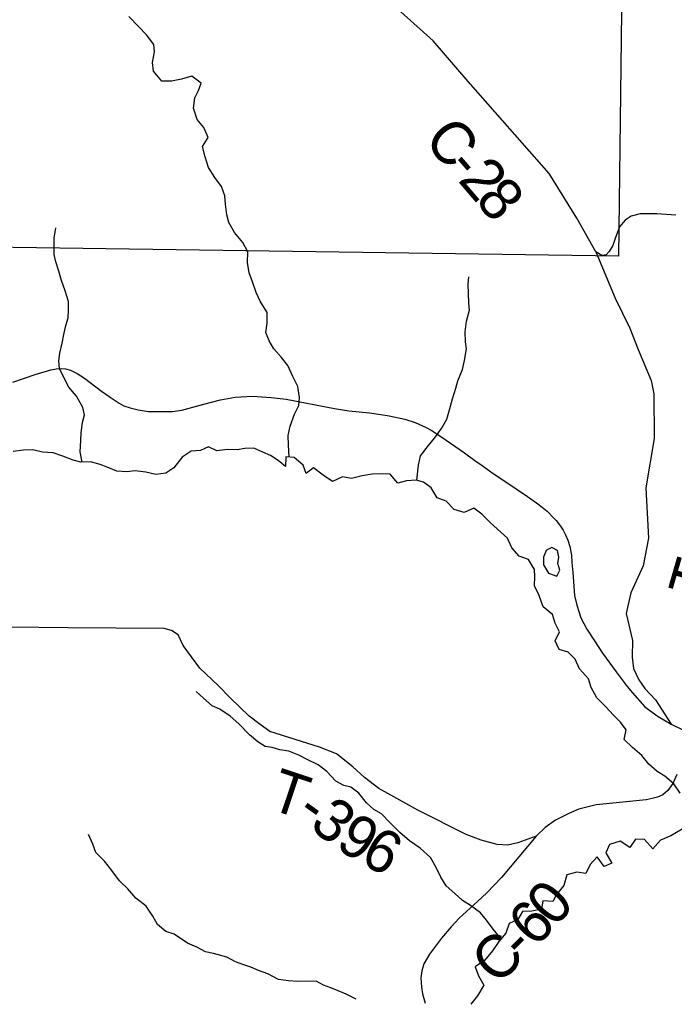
# Model space of a CAD drawing. Extents: x -20.5 to 34, y -66 to 23.9.
# Drawn here: x 7.132 to 8.003, y 16.344 to 17.643 of the extents above; entities that cross this region are included whole.
import ezdxf

# ---------------------------------------------------------------- set-up
doc = ezdxf.new("R2010")
doc.units = 0
for name, color, linetype in [('GM_X_County_Text', 7, 'Continuous'), ('GM_X_Minor_Lake', 7, 'Continuous'), ('GM_X_Minor_River', 7, 'Continuous'), ('GM_X_Minor_River_Text', 7, 'Continuous'), ('GM_X_Section_Text', 7, 'Continuous'), ('GM_X_State_Route', 7, 'Continuous'), ('GM_X_Township_Road', 7, 'Continuous'), ('GM_X_Township_Road_Text', 7, 'Continuous')]:
    doc.layers.add(name, color=color, linetype=linetype)

msp = doc.modelspace()

# ---------------------------------------------------------------- linework, layer by layer
at = {"layer": 'GM_X_County_Text'}
for points in [[(7.8986, 17.3346), (7.924, 17.2728), (7.9438, 17.2332), (7.9545, 17.2047), (7.9719, 17.1637), (7.9754, 17.1456), (7.9761, 17.0866), (7.9647, 17.0209), (7.9685, 16.9541), (7.9614, 16.9171), (7.9451, 16.8813), (7.9422, 16.87), (7.9386, 16.8541), (7.947, 16.8183), (7.9466, 16.7959), (7.9483, 16.7807), (7.9555, 16.7657), (7.9637, 16.7545), (7.9778, 16.7393), (7.9984, 16.7071)], [(7.8192, 16.5583), (7.7947, 16.5495), (7.7812, 16.5464), (7.7672, 16.5472), (7.7458, 16.5528), (7.726, 16.5606), (7.6616, 16.5929), (7.6098, 16.6215), (7.591, 16.6362), (7.5753, 16.6501), (7.5535, 16.6677), (7.531, 16.6763), (7.465, 16.6974), (7.4522, 16.7067), (7.4378, 16.7175), (7.4129, 16.7415), (7.3962, 16.7582), (7.3721, 16.7815), (7.3497, 16.8115), (7.3432, 16.8256), (7.3342, 16.8316), (7.3246, 16.834), (7.1972, 16.835), (7.119, 16.8357)]]:
    msp.add_lwpolyline(points, dxfattribs=at)
at = {"layer": 'GM_X_Minor_Lake'}
msp.add_lwpolyline([(7.9409, 18.3387), (7.9284, 17.3287), (7.0924, 17.3404), (6.9259, 17.3432), (6.9356, 18.3607)], close=True, dxfattribs=at)
at = {"layer": 'GM_X_Minor_River'}
for points in [[(7.8355, 16.9394), (7.8322, 16.9377), (7.8289, 16.9289), (7.8287, 16.9187), (7.8354, 16.9074), (7.8467, 16.9034)], [(7.8467, 16.9034), (7.8507, 16.9114), (7.848, 16.9205), (7.8493, 16.9289), (7.8473, 16.9376), (7.8401, 16.9416), (7.8355, 16.9394)]]:
    msp.add_lwpolyline(points, dxfattribs=at)
at = {"layer": 'GM_X_Minor_River_Text'}
for points in [[(7.4906, 17.0619), (7.4899, 17.0775), (7.4893, 17.0904), (7.4922, 17.103), (7.498, 17.1186), (7.5035, 17.1301), (7.5044, 17.1411), (7.5023, 17.1555), (7.4957, 17.169), (7.489, 17.1833), (7.4805, 17.1942), (7.4702, 17.2054), (7.4643, 17.216), (7.4596, 17.2273), (7.4617, 17.2398), (7.4615, 17.2539), (7.4522, 17.2689), (7.4467, 17.2806), (7.4419, 17.2946), (7.4376, 17.3066), (7.4355, 17.3203), (7.436, 17.3343), (7.429, 17.3467), (7.4182, 17.3602), (7.4105, 17.3734), (7.408, 17.3836), (7.4063, 17.3976), (7.4054, 17.4086), (7.4007, 17.421), (7.3918, 17.433), (7.3836, 17.4466), (7.3793, 17.4605), (7.3756, 17.4741), (7.383, 17.4864), (7.3775, 17.4996), (7.3683, 17.5104), (7.3635, 17.5252), (7.3652, 17.5388), (7.3703, 17.5488), (7.374, 17.5583), (7.3613, 17.5676), (7.3478, 17.5636), (7.3342, 17.5611), (7.3217, 17.5609), (7.3105, 17.5744), (7.3092, 17.5858), (7.3117, 17.6002), (7.3108, 17.6097), (7.3011, 17.6225), (7.2903, 17.6337), (7.2776, 17.6471)], [(7.2156, 17.0548), (7.213, 17.0688), (7.2139, 17.084), (7.2142, 17.0939), (7.2162, 17.1075), (7.2187, 17.1178), (7.2167, 17.1277), (7.2081, 17.1427), (7.1977, 17.1547), (7.1911, 17.1675), (7.1856, 17.1795), (7.1847, 17.1898), (7.1861, 17.2), (7.1889, 17.213), (7.1914, 17.2248), (7.1938, 17.2366), (7.1971, 17.2469), (7.1973, 17.2567), (7.1975, 17.2685), (7.1931, 17.2825), (7.188, 17.2964), (7.1844, 17.3089), (7.1805, 17.321), (7.1784, 17.3308), (7.1783, 17.341), (7.1785, 17.3524), (7.1805, 17.3661)], [(7.6604, 17.0309), (7.6625, 17.0509), (7.6653, 17.0635), (7.6761, 17.0773), (7.6839, 17.0869), (7.6935, 17.0999), (7.7005, 17.1122), (7.7041, 17.1244), (7.7077, 17.1392), (7.7124, 17.1533), (7.7149, 17.1632), (7.7211, 17.1781), (7.7239, 17.1899), (7.7263, 17.2055), (7.7254, 17.215), (7.7248, 17.2282), (7.7265, 17.2423), (7.7305, 17.2568), (7.7296, 17.2666), (7.729, 17.2787), (7.7288, 17.2913), (7.7294, 17.3011)], [(8.0107, 16.6152), (8.0022, 16.6276), (7.99, 16.6377), (7.98, 16.644), (7.9689, 16.6537), (7.9597, 16.6653), (7.9474, 16.6761), (7.9362, 16.6866), (7.9387, 16.6995), (7.9314, 16.7097), (7.9218, 16.719), (7.9118, 16.7302), (7.8998, 16.7418), (7.8924, 16.7557), (7.8889, 16.7671), (7.8766, 16.7805), (7.8711, 16.7934), (7.8615, 16.8027), (7.8497, 16.8063), (7.8446, 16.8176), (7.8501, 16.8295), (7.8442, 16.8411), (7.8407, 16.8525), (7.8284, 16.8629), (7.8229, 16.878), (7.817, 16.8908), (7.8172, 16.903), (7.817, 16.9125), (7.8089, 16.9256), (7.7967, 16.93), (7.7867, 16.9412), (7.7808, 16.954), (7.7678, 16.966), (7.7574, 16.9753), (7.7471, 16.9861), (7.7363, 16.994), (7.7236, 16.9881), (7.7103, 16.992), (7.6995, 17.0033), (7.6877, 17.0076), (7.6796, 17.0208), (7.6692, 17.0286), (7.6597, 17.0311), (7.6469, 17.0302), (7.6352, 17.027), (7.6252, 17.039), (7.6153, 17.0396), (7.6013, 17.039), (7.5877, 17.0369), (7.5738, 17.0332), (7.5617, 17.0357), (7.5485, 17.0295), (7.5359, 17.0376), (7.5233, 17.0473), (7.5135, 17.0399), (7.5096, 17.0509), (7.4973, 17.0613), (7.4863, 17.0623), (7.4858, 17.0494), (7.4762, 17.0572), (7.4659, 17.0639), (7.4556, 17.0683), (7.4438, 17.0734), (7.4317, 17.0732), (7.4215, 17.0712), (7.409, 17.0717), (7.3946, 17.07), (7.3836, 17.0752), (7.3731, 17.0705), (7.3606, 17.0695), (7.3486, 17.0617), (7.3375, 17.0475), (7.327, 17.0405), (7.3134, 17.0388), (7.3001, 17.0417), (7.2861, 17.0433), (7.2747, 17.042), (7.2619, 17.043), (7.2489, 17.0485), (7.2394, 17.0517), (7.2269, 17.0554), (7.214, 17.0548), (7.2038, 17.0577), (7.19, 17.0631), (7.1771, 17.0675), (7.1631, 17.0684), (7.1502, 17.0716), (7.1377, 17.0711), (7.1241, 17.069)], [(7.7724, 16.4217), (7.7618, 16.4347), (7.7533, 16.4467), (7.7452, 16.4564), (7.7318, 16.4661), (7.7211, 16.4728), (7.7112, 16.4821), (7.6997, 16.4922), (7.6923, 16.5038), (7.6861, 16.5166), (7.6787, 16.5298), (7.6649, 16.5421), (7.6507, 16.5518), (7.6381, 16.563), (7.625, 16.5757), (7.6135, 16.588), (7.6032, 16.5936), (7.5936, 16.6025), (7.5835, 16.6153), (7.5728, 16.6231), (7.5633, 16.6256), (7.553, 16.6311), (7.5407, 16.6439), (7.5292, 16.6528), (7.5155, 16.6598), (7.5037, 16.6657), (7.4904, 16.6712), (7.4782, 16.6729), (7.4684, 16.6758), (7.4589, 16.6772), (7.4493, 16.6835), (7.4382, 16.6928), (7.424, 16.7074), (7.4125, 16.7178), (7.3987, 16.7271), (7.3884, 16.7311), (7.3769, 16.7416), (7.3673, 16.7502)], [(8.013, 16.5675), (7.9983, 16.5585), (7.9844, 16.553), (7.974, 16.5414), (7.9632, 16.5538), (7.9511, 16.5544), (7.9437, 16.5433), (7.9307, 16.5514), (7.9164, 16.547), (7.9117, 16.536), (7.9198, 16.5224), (7.9097, 16.5181), (7.9, 16.5308), (7.8907, 16.5205), (7.8852, 16.5086), (7.8731, 16.5103), (7.8599, 16.5067), (7.8559, 16.4926), (7.8463, 16.4807), (7.8415, 16.4712), (7.8282, 16.4725), (7.8261, 16.4611), (7.8133, 16.4586), (7.8008, 16.458), (7.7949, 16.4477), (7.7833, 16.4422), (7.7789, 16.4292), (7.7693, 16.4181), (7.7611, 16.4058), (7.7507, 16.3935), (7.738, 16.3846), (7.7423, 16.3725), (7.7497, 16.3601), (7.7412, 16.3459), (7.7323, 16.3352)], [(7.5797, 16.3416), (7.5667, 16.3483), (7.5561, 16.3527), (7.5462, 16.3567), (7.5363, 16.3603), (7.5268, 16.3655), (7.5018, 16.3651), (7.4897, 16.3661), (7.4768, 16.3678), (7.4623, 16.3755), (7.4501, 16.3799), (7.4398, 16.3843), (7.4292, 16.3876), (7.4193, 16.3912), (7.4078, 16.3975), (7.39, 16.4025), (7.3797, 16.4047), (7.3679, 16.4106), (7.3557, 16.4161), (7.3378, 16.4279), (7.3267, 16.4316), (7.3156, 16.4409), (7.3094, 16.4518), (7.3009, 16.465), (7.2871, 16.4758), (7.2763, 16.4881), (7.2652, 16.499), (7.2551, 16.5128), (7.2455, 16.5248), (7.2336, 16.5364), (7.2296, 16.5477), (7.2241, 16.5606)]]:
    msp.add_lwpolyline(points, dxfattribs=at)
at = {"layer": 'GM_X_State_Route'}
for points in [[(8.0049, 17.3833), (7.9794, 17.3849), (7.9572, 17.3849), (7.9452, 17.3819), (7.9373, 17.3766), (7.9299, 17.3675), (7.924, 17.3521), (7.921, 17.3428), (7.9163, 17.3347), (7.912, 17.3303), (7.9066, 17.3295), (7.8986, 17.3346), (7.8734, 17.379), (7.8366, 17.4384), (7.7289, 17.5606), (7.6824, 17.6149), (7.6265, 17.6649)], [(8.006, 16.64), (8.0007, 16.6282), (7.994, 16.6187), (7.9874, 16.613), (7.9804, 16.6101), (7.9735, 16.6082), (7.9654, 16.6066), (7.9477, 16.6046), (7.8988, 16.5998), (7.876, 16.594), (7.8626, 16.5885), (7.8449, 16.5796), (7.8311, 16.5696), (7.8192, 16.5583), (7.7729, 16.5032), (7.7534, 16.4831), (7.7413, 16.4715), (7.7167, 16.4491), (7.7062, 16.4378), (7.6934, 16.4228), (7.6839, 16.4101), (7.6775, 16.4015), (7.6698, 16.3884), (7.667, 16.3791), (7.6656, 16.3698), (7.6668, 16.3576), (7.6682, 16.3487), (7.6714, 16.3363)]]:
    msp.add_lwpolyline(points, dxfattribs=at)
at = {"layer": 'GM_X_Township_Road'}
msp.add_lwpolyline([(7.1233, 17.1611), (7.1531, 17.1714), (7.1738, 17.1776), (7.1811, 17.1792), (7.1881, 17.1794), (7.1933, 17.1791), (7.2002, 17.1774), (7.209, 17.173), (7.2185, 17.1664), (7.2411, 17.1494), (7.2527, 17.1415), (7.2649, 17.1335), (7.2709, 17.13), (7.2793, 17.127), (7.2902, 17.1244), (7.3039, 17.1224), (7.3194, 17.1221), (7.3357, 17.1224), (7.3483, 17.1239), (7.3773, 17.1322), (7.3995, 17.1378), (7.4189, 17.1415), (7.4422, 17.1428), (7.4668, 17.1411), (7.4868, 17.1385), (7.5509, 17.1262), (7.57, 17.1232), (7.5975, 17.1205), (7.6128, 17.1185), (7.6237, 17.1165), (7.6446, 17.1122), (7.6583, 17.1078), (7.673, 17.1009), (7.6794, 17.0976), (7.6938, 17.0884), (7.7237, 17.0673), (7.7378, 17.0573), (7.7475, 17.0504), (7.7621, 17.04), (7.7788, 17.0287), (7.8076, 17.0092), (7.8197, 17.0009), (7.8269, 16.9951), (7.8336, 16.9898), (7.8422, 16.9812), (7.8456, 16.9774), (7.8515, 16.97), (7.8549, 16.9647), (7.8581, 16.9583), (7.8613, 16.9512), (7.8637, 16.9428), (7.8659, 16.9314), (7.8664, 16.9215), (7.8677, 16.9083), (7.8699, 16.8779), (7.8733, 16.8649), (7.8787, 16.8481), (7.8864, 16.8331), (7.8966, 16.8175), (7.9075, 16.8014), (7.9253, 16.7764), (7.9403, 16.7568), (7.9471, 16.7484), (7.9637, 16.73), (7.9815, 16.7171), (7.9984, 16.7071), (8.0139, 16.6994)], dxfattribs=at)

# ---------------------------------------------------------------- texts
at = {"layer": 'GM_X_Section_Text'}
for s, rotation, p in [('T', 73.9781, (8.0489, 16.8711)), ('T', 341.4146, (7.4616, 16.5954)), ('-', 324.4337, (7.4979, 16.5839)), ('3', 320.423, (7.5161, 16.5709)), ('9', 328.8432, (7.5505, 16.5434)), ('6', 331.7368, (7.5831, 16.5237))]:
    msp.add_text(s, height=0.0568, rotation=rotation, dxfattribs=at).set_placement(p)
at = {"layer": 'GM_X_Township_Road_Text'}
for s, rotation, p in [('C', 310.7431, (7.6683, 17.4822)), ('-', 310.7241, (7.6988, 17.4468)), ('2', 310.6261, (7.714, 17.4292)), ('8', 310.1571, (7.7367, 17.4027)), ('0', 48.1199, (7.8438, 16.4358)), ('6', 46.2013, (7.8182, 16.409)), ('C', 45.0345, (7.7679, 16.3585)), ('-', 45.3225, (7.8011, 16.3917))]:
    msp.add_text(s, height=0.0568, rotation=rotation, dxfattribs=at).set_placement(p)

doc.saveas('drawing.dxf')
